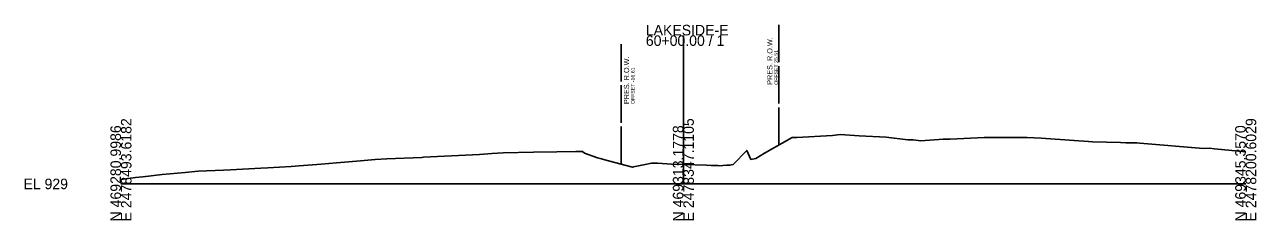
# Model space of a CAD drawing. Extents: x -26 to 2478923, y -10 to 469990.
# Drawn here: x -25.7 to 302.8, y 10490.3 to 10542.4 of the extents above; entities that cross this region are included whole.
import ezdxf

# ---------------------------------------------------------------- set-up
doc = ezdxf.new("R2010")
doc.units = 0
for name, color, linetype in [('DESIGN - SHEET - Light Grid', 7, 'Continuous'), ('SURVEY - GROUND - Top of Ground', 7, 'Continuous'), ('SURVEY - PROPERTY - ROW Lines', 7, 'Continuous'), ('SURVEY - PROPERTY - ROW Lines Text', 7, 'Continuous')]:
    doc.layers.add(name, color=color, linetype=linetype)

msp = doc.modelspace()

# ---------------------------------------------------------------- linework, layer by layer
at = {"layer": 'DESIGN - SHEET - Light Grid'}
for p, q in [((150, 10500), (150, 10539.55)), ((0, 10500), (150, 10500)), ((150, 10500), (300, 10500))]:
    msp.add_line(p, q, dxfattribs=at)
at = {"layer": 'SURVEY - GROUND - Top of Ground'}
msp.add_lwpolyline([(0, 10501.21), (3.87, 10501.67), (5.8, 10501.91), (10.97, 10502.47), (17.1, 10503.02), (20.55, 10503.35), (27.36, 10503.63), (29.25, 10503.72), (37.29, 10504.18), (39.18, 10504.28), (45.4, 10504.61), (47.51, 10504.78), (53.37, 10505.29), (57.53, 10505.63), (63.88, 10506.15), (67.77, 10506.46), (70.87, 10506.64), (80.22, 10507.07), (80.71, 10507.09), (88.18, 10507.5), (95.62, 10507.87), (98.92, 10508.09), (101.91, 10508.24), (110.01, 10508.45), (116.23, 10508.55), (121.32, 10508.63), (123.12, 10508.65), (123.61, 10508.2), (127.09, 10506.97), (127.78, 10506.76), (130.02, 10506.14), (136.44, 10504.44), (136.68, 10504.54), (139.78, 10505.13), (141.54, 10505.48), (142.09, 10505.49), (143.1, 10505.48), (146.8, 10505.3), (150, 10505.21), (156.19, 10505.03), (157.38, 10504.91), (159.19, 10504.92), (159.56, 10504.85), (161.47, 10504.95), (162.07, 10504.99), (162.42, 10504.96), (162.74, 10505.04), (163.26, 10505.13), (166.93, 10508.94), (168.04, 10506.51), (169.31, 10506.8), (171.61, 10508.16), (179.05, 10512.39), (180.27, 10512.33), (189.76, 10512.91), (191.83, 10513.18), (196.94, 10512.83), (204.06, 10512.48), (209.84, 10511.7), (211.33, 10511.73), (213.36, 10511.49), (219.32, 10511.91), (221.19, 10511.95), (230.28, 10512.37), (233.7, 10512.32), (241.71, 10512.38), (245.47, 10512.2), (254.21, 10511.54), (258.03, 10511.25), (259.16, 10511.2), (266.64, 10511.02), (268, 10510.97), (270.96, 10510.9), (271.73, 10510.84), (288.7, 10509.47), (290.32, 10509.48), (291.67, 10509.33), (300, 10508.55)], dxfattribs=at)
at = {"layer": 'SURVEY - PROPERTY - ROW Lines'}
for p, q in [((175.51, 10532.38), (175.51, 10542.38)), ((133.39, 10527.25), (133.39, 10537.25)), ((175.51, 10521.38), (175.51, 10531.38)), ((133.39, 10516.25), (133.39, 10526.25)), ((175.51, 10510.38), (175.51, 10520.38)), ((133.39, 10505.25), (133.39, 10515.25))]:
    msp.add_line(p, q, dxfattribs=at)

# ---------------------------------------------------------------- texts
at = {"layer": 'DESIGN - SHEET - Light Grid'}
for s, p in [('60+00.00 / 1', (140, 10536.75)), ('LAKESIDE-E', (140, 10539.55)), ('EL 929', (-26, 10498.6))]:
    msp.add_text(s, height=2.8, dxfattribs=at).set_placement(p)
for s, p in [('E 2478493.6182', (2.8, 10490)), ('E 2478347.1105', (152.8, 10490)), ('E 2478200.6029', (302.8, 10490)), ('N 469280.9986', (0, 10490)), ('N 469313.1778', (150, 10490)), ('N 469345.3570', (300, 10490))]:
    msp.add_text(s, height=2.8, rotation=90, dxfattribs=at).set_placement(p)
at = {"layer": 'SURVEY - PROPERTY - ROW Lines Text'}
for s, height, p in [('PRES. R.O.W.', 1.4, (173.76, 10526.38)), ('PRES. R.O.W.', 1.4, (135.54, 10521.25)), ('OFFSET 25.51', 1, (175.26, 10526.38)), ('OFFSET -16.61', 1, (137.04, 10521.25))]:
    msp.add_text(s, height=height, rotation=90, dxfattribs=at).set_placement(p)

doc.saveas('drawing.dxf')
